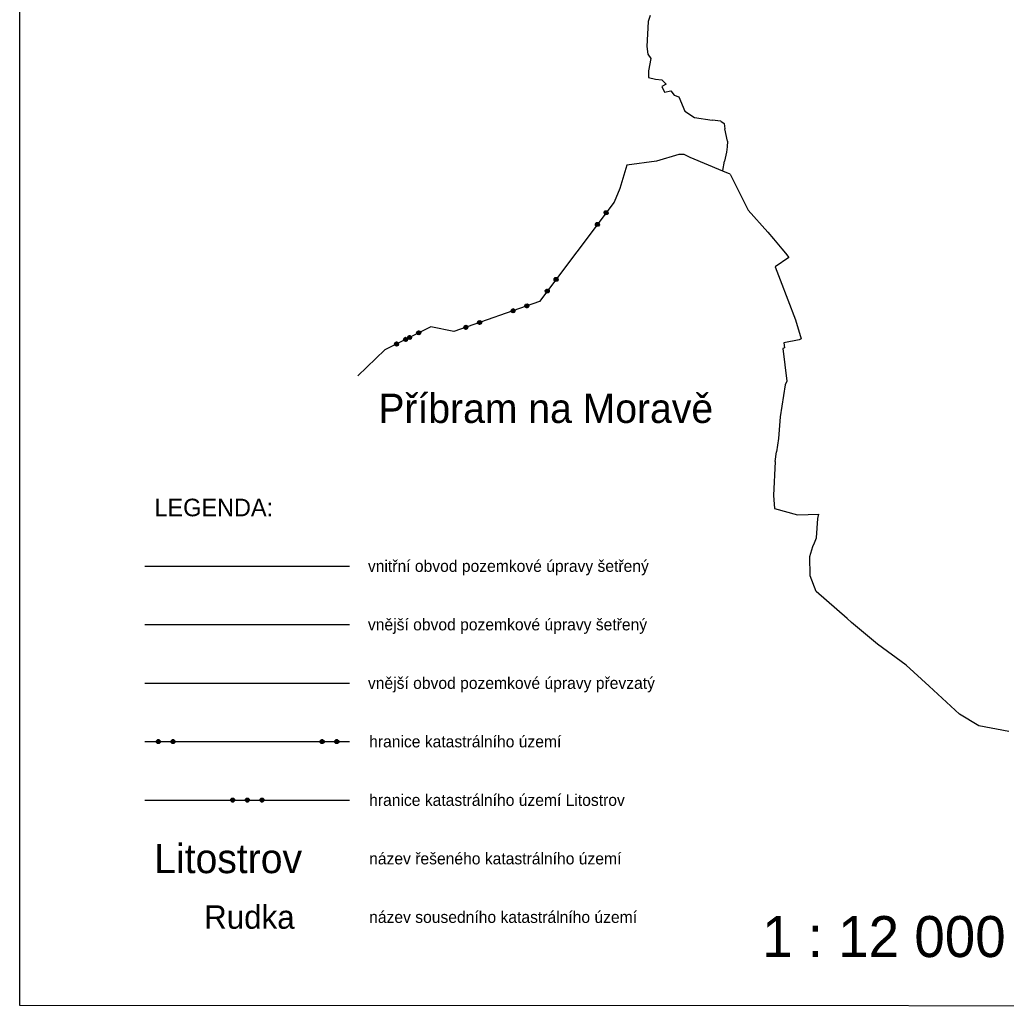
# Model space of a CAD drawing. Extents: x -619641 to -615981, y -1158223 to -1153120.
# Drawn here: x -619641 to -617618, y -1158223 to -1156200 of the extents above; entities that cross this region are included whole.
import ezdxf

# ---------------------------------------------------------------- set-up
doc = ezdxf.new("R2010")
doc.units = 0
for name, color, linetype in [('HRA_KU', 7, 'Continuous'), ('LEGENDA', 7, 'Continuous'), ('Level 255', 7, 'Continuous'), ('POPIS', 7, 'Continuous'), ('RAM', 7, 'Continuous')]:
    doc.layers.add(name, color=color, linetype=linetype)

msp = doc.modelspace()

# ---------------------------------------------------------------- linework, layer by layer
at = {"layer": 'HRA_KU'}
for p, q in [((-618347.7, -1156190.9), (-618352.3, -1156203.8)), ((-618352.3, -1156203.8), (-618355, -1156255.1)), ((-618355, -1156255.1), (-618353, -1156270.5)), ((-618353, -1156270.5), (-618346.8, -1156279.5)), ((-618346.8, -1156279.5), (-618351.4, -1156304.8)), ((-618351.4, -1156304.8), (-618351.7, -1156318.1)), ((-618351.7, -1156318.1), (-618337.3, -1156322.1)), ((-618337.3, -1156322.1), (-618323.8, -1156323.4)), ((-618323.8, -1156323.4), (-618314.9, -1156331.8)), ((-618314.9, -1156331.8), (-618323.8, -1156336.6)), ((-618323.8, -1156336.6), (-618318.3, -1156348.3)), ((-618318.3, -1156348.3), (-618305.6, -1156345.7)), ((-618305.6, -1156345.7), (-618298.5, -1156354.8)), ((-618298.5, -1156354.8), (-618289, -1156357.8)), ((-618289, -1156357.8), (-618277.1, -1156387.6)), ((-618277.1, -1156387.6), (-618256.9, -1156400.6)), ((-618256.9, -1156400.6), (-618221, -1156406.2)), ((-618203.3, -1156408), (-618221, -1156406.2)), ((-618203.3, -1156408), (-618195.9, -1156412.8)), ((-618195.9, -1156412.8), (-618194.5, -1156423.7)), ((-618189.1, -1156449.2), (-618194.5, -1156423.7)), ((-618189.1, -1156449.2), (-618189.8, -1156460.4)), ((-618191.3, -1156471.6), (-618195.4, -1156490.1)), ((-618189.8, -1156460.4), (-618191.3, -1156471.6)), ((-618198.8, -1156508.9), (-618195.4, -1156490.1)), ((-618199.1, -1156510.7), (-618198.8, -1156508.9)), ((-618184.2, -1156516.9), (-618199.1, -1156510.7)), ((-618184.2, -1156516.9), (-618146.7, -1156590.3)), ((-618146.7, -1156590.3), (-618106.3, -1156635.9)), ((-618106.3, -1156635.9), (-618095.2, -1156649.2)), ((-618095.2, -1156649.2), (-618077.9, -1156669.9)), ((-618077.9, -1156669.9), (-618070.4, -1156679)), ((-618063.2, -1156687.6), (-618091.8, -1156706.9)), ((-618070.4, -1156679), (-618063.2, -1156687.6)), ((-618091.8, -1156706.9), (-618081.1, -1156733.3)), ((-618081.1, -1156733.3), (-618050, -1156815.1)), ((-618050, -1156815.1), (-618038, -1156854.2)), ((-618042.6, -1156856.2), (-618074.1, -1156862.7)), ((-618038, -1156854.2), (-618042.6, -1156856.2)), ((-618072.3, -1156872.8), (-618075.7, -1156874.2)), ((-618075.7, -1156874.2), (-618067.8, -1156941.1)), ((-618074.1, -1156862.7), (-618072.3, -1156872.8)), ((-618071.2, -1156948.6), (-618081.2, -1157014.1)), ((-618067.8, -1156941.1), (-618071.2, -1156948.6)), ((-618081.2, -1157014.1), (-618084.5, -1157059.1)), ((-618084.5, -1157059.1), (-618088.8, -1157086)), ((-618091.4, -1157106.2), (-618088.8, -1157086)), ((-618091.4, -1157106.2), (-618095.1, -1157175.7)), ((-618095.1, -1157175.7), (-618093, -1157202.7)), ((-618093, -1157202.7), (-618045.9, -1157215.6)), ((-618045.9, -1157215.6), (-618001.7, -1157214)), ((-618006.8, -1157262.8), (-618004, -1157223.1)), ((-618004, -1157223.1), (-618001.7, -1157214)), ((-618010.9, -1157272.5), (-618006.8, -1157262.8)), ((-618020.7, -1157300.6), (-618014.3, -1157280.4)), ((-618014.3, -1157280.4), (-618010.9, -1157272.5)), ((-618019.7, -1157340.2), (-618020.7, -1157300.6)), ((-618007.4, -1157372.9), (-618019.7, -1157340.2)), ((-617944.1, -1157428.2), (-618007.4, -1157372.9)), ((-617934.7, -1157436.1), (-617944.1, -1157428.2)), ((-617881.5, -1157480.6), (-617934.7, -1157436.1)), ((-617822.7, -1157523.6), (-617881.5, -1157480.6)), ((-617775.7, -1157566.9), (-617822.7, -1157523.6)), ((-617713.4, -1157624.2), (-617775.7, -1157566.9)), ((-617673.7, -1157647.9), (-617713.4, -1157624.2)), ((-617612, -1157659.7), (-617673.7, -1157647.9))]:
    msp.add_line(p, q, dxfattribs=at)
for points in [[(-618199.1, -1156510.7), (-618266.1, -1156482.7), (-618278.3, -1156476.6), (-618289.1, -1156476.5), (-618335, -1156489.7), (-618396, -1156498.4), (-618410.2, -1156545.8), (-618421.7, -1156573.8), (-618574.8, -1156777.7), (-618750.9, -1156839.6), (-618798.2, -1156829.7), (-618891.9, -1156877.1), (-618947.7, -1156930.5)], [(-618436.1, -1156599.4), (-618439.3, -1156599.8), (-618441.9, -1156597.9), (-618442.3, -1156594.7), (-618440.4, -1156592.1), (-618437.2, -1156591.7), (-618434.6, -1156593.6), (-618434.2, -1156596.8), (-618436.1, -1156599.4), (-618436.4, -1156599), (-618434.7, -1156596.7), (-618434.9, -1156595.4), (-618437.8, -1156599.2), (-618439.1, -1156599.4), (-618435.1, -1156594), (-618435.8, -1156593.4), (-618439.9, -1156598.8), (-618440.6, -1156598.2), (-618436.6, -1156592.9), (-618437.4, -1156592.3), (-618441.4, -1156597.7), (-618441.6, -1156596.3), (-618438.7, -1156592.5), (-618440.1, -1156592.7), (-618441.8, -1156595)], [(-618454.1, -1156623.4), (-618457.3, -1156623.8), (-618459.9, -1156621.9), (-618460.4, -1156618.7), (-618458.4, -1156616.1), (-618455.2, -1156615.6), (-618452.6, -1156617.6), (-618452.2, -1156620.8), (-618454.1, -1156623.4), (-618454.3, -1156622.8), (-618452.6, -1156620.5), (-618452.8, -1156619.2), (-618455.6, -1156623), (-618457, -1156623.2), (-618452.9, -1156617.8), (-618453.7, -1156617.2), (-618457.7, -1156622.6), (-618458.5, -1156622), (-618454.5, -1156616.7), (-618455.2, -1156616.1), (-618459.3, -1156621.5), (-618459.5, -1156620.1), (-618456.6, -1156616.3), (-618457.9, -1156616.5), (-618459.7, -1156618.8)], [(-618538.8, -1156736.2), (-618542, -1156736.6), (-618544.6, -1156734.7), (-618545.1, -1156731.5), (-618543.1, -1156728.9), (-618539.9, -1156728.4), (-618537.3, -1156730.4), (-618536.9, -1156733.6), (-618538.8, -1156736.2), (-618539.2, -1156735.8), (-618537.4, -1156733.5), (-618537.6, -1156732.1), (-618540.5, -1156736), (-618541.8, -1156736.2), (-618537.8, -1156730.8), (-618538.6, -1156730.2), (-618542.6, -1156735.6), (-618543.4, -1156735), (-618539.3, -1156729.6), (-618540.1, -1156729.1), (-618544.1, -1156734.4), (-618544.3, -1156733.1), (-618541.5, -1156729.3), (-618542.8, -1156729.4), (-618544.5, -1156731.7)], [(-618556.9, -1156760.2), (-618560.1, -1156760.6), (-618562.6, -1156758.7), (-618563.1, -1156755.5), (-618561.2, -1156752.9), (-618558, -1156752.4), (-618555.4, -1156754.4), (-618554.9, -1156757.6), (-618556.9, -1156760.2), (-618557, -1156759.6), (-618555.3, -1156757.3), (-618555.5, -1156755.9), (-618558.4, -1156759.8), (-618559.7, -1156760), (-618555.7, -1156754.6), (-618556.5, -1156754), (-618560.5, -1156759.4), (-618561.3, -1156758.8), (-618557.2, -1156753.4), (-618558, -1156752.9), (-618562, -1156758.2), (-618562.2, -1156756.9), (-618559.3, -1156753), (-618560.7, -1156753.2), (-618562.4, -1156755.5)], [(-618629.4, -1156800.9), (-618632.3, -1156799.5), (-618633.4, -1156796.5), (-618632, -1156793.6), (-618628.9, -1156792.5), (-618626, -1156793.9), (-618624.9, -1156797), (-618626.3, -1156799.9), (-618629.4, -1156800.9), (-618629.2, -1156800.4), (-618626.5, -1156799.4), (-618625.9, -1156798.2), (-618630.4, -1156799.8), (-618631.7, -1156799.2), (-618625.3, -1156797), (-618625.6, -1156796.1), (-618632, -1156798.3), (-618632.3, -1156797.4), (-618626, -1156795.2), (-618626.3, -1156794.2), (-618632.6, -1156796.5), (-618632, -1156795.2), (-618627.5, -1156793.7), (-618628.7, -1156793.1), (-618631.4, -1156794)], [(-618601.1, -1156791), (-618604, -1156789.6), (-618605.1, -1156786.6), (-618603.7, -1156783.6), (-618600.6, -1156782.6), (-618597.7, -1156784), (-618596.6, -1156787), (-618598, -1156789.9), (-618601.1, -1156791), (-618601.1, -1156790.5), (-618598.4, -1156789.6), (-618597.8, -1156788.3), (-618602.4, -1156789.9), (-618603.6, -1156789.3), (-618597.2, -1156787.1), (-618597.6, -1156786.2), (-618603.9, -1156788.4), (-618604.2, -1156787.5), (-618597.9, -1156785.3), (-618598.2, -1156784.4), (-618604.5, -1156786.6), (-618603.9, -1156785.4), (-618599.4, -1156783.8), (-618600.6, -1156783.2), (-618603.4, -1156784.2)], [(-618697.9, -1156825), (-618700.8, -1156823.6), (-618701.9, -1156820.6), (-618700.5, -1156817.7), (-618697.4, -1156816.6), (-618694.5, -1156818), (-618693.5, -1156821), (-618694.9, -1156823.9), (-618697.9, -1156825), (-618698, -1156824.5), (-618695.2, -1156823.6), (-618694.7, -1156822.4), (-618699.2, -1156823.9), (-618700.4, -1156823.4), (-618694.1, -1156821.1), (-618694.4, -1156820.2), (-618700.7, -1156822.4), (-618701, -1156821.5), (-618694.7, -1156819.3), (-618695, -1156818.4), (-618701.4, -1156820.6), (-618700.8, -1156819.4), (-618696.2, -1156817.8), (-618697.5, -1156817.2), (-618700.2, -1156818.2)], [(-618822.5, -1156846.3), (-618825.6, -1156845.3), (-618827, -1156842.4), (-618826, -1156839.3), (-618823.1, -1156837.8), (-618820.1, -1156838.8), (-618818.6, -1156841.7), (-618819.6, -1156844.8), (-618822.5, -1156846.3), (-618822.6, -1156845.8), (-618820.1, -1156844.5), (-618819.6, -1156843.2), (-618823.9, -1156845.4), (-618825.2, -1156844.9), (-618819.2, -1156841.9), (-618819.6, -1156841), (-618825.6, -1156844.1), (-618826.1, -1156843.2), (-618820.1, -1156840.2), (-618820.5, -1156839.3), (-618826.5, -1156842.4), (-618826.1, -1156841.1), (-618821.8, -1156838.9), (-618823.1, -1156838.5), (-618825.7, -1156839.8)], [(-618726.2, -1156835), (-618729.1, -1156833.6), (-618730.2, -1156830.5), (-618728.8, -1156827.6), (-618725.8, -1156826.5), (-618722.8, -1156827.9), (-618721.8, -1156831), (-618723.2, -1156833.9), (-618726.2, -1156835), (-618726, -1156834.4), (-618723.3, -1156833.4), (-618722.7, -1156832.2), (-618727.3, -1156833.8), (-618728.5, -1156833.2), (-618722.2, -1156831), (-618722.5, -1156830.1), (-618728.8, -1156832.3), (-618729.1, -1156831.4), (-618722.8, -1156829.2), (-618723.1, -1156828.3), (-618729.4, -1156830.5), (-618728.9, -1156829.3), (-618724.3, -1156827.7), (-618725.6, -1156827.1), (-618728.3, -1156828)], [(-618849.3, -1156859.8), (-618852.3, -1156858.8), (-618853.8, -1156855.9), (-618852.8, -1156852.8), (-618849.9, -1156851.4), (-618846.8, -1156852.4), (-618845.4, -1156855.3), (-618846.4, -1156858.3), (-618849.3, -1156859.8), (-618849.2, -1156859.2), (-618846.6, -1156857.9), (-618846.2, -1156856.6), (-618850.5, -1156858.8), (-618851.8, -1156858.4), (-618845.8, -1156855.3), (-618846.2, -1156854.5), (-618852.2, -1156857.5), (-618852.6, -1156856.7), (-618846.6, -1156853.6), (-618847.1, -1156852.8), (-618853.1, -1156855.8), (-618852.6, -1156854.5), (-618848.3, -1156852.3), (-618849.6, -1156851.9), (-618852.2, -1156853.2)], [(-618841.2, -1156855.7), (-618844.3, -1156854.7), (-618845.7, -1156851.8), (-618844.7, -1156848.8), (-618841.8, -1156847.3), (-618838.8, -1156848.3), (-618837.3, -1156851.2), (-618838.3, -1156854.3), (-618841.2, -1156855.7), (-618841.3, -1156855.2), (-618838.7, -1156853.9), (-618838.3, -1156852.6), (-618842.6, -1156854.8), (-618843.9, -1156854.4), (-618837.9, -1156851.4), (-618838.3, -1156850.5), (-618844.3, -1156853.5), (-618844.8, -1156852.7), (-618838.8, -1156849.6), (-618839.2, -1156848.8), (-618845.2, -1156851.8), (-618844.8, -1156850.5), (-618840.5, -1156848.4), (-618841.8, -1156847.9), (-618844.3, -1156849.2)], [(-618868, -1156869.3), (-618871, -1156868.3), (-618872.5, -1156865.4), (-618871.5, -1156862.3), (-618868.6, -1156860.8), (-618865.5, -1156861.8), (-618864.1, -1156864.7), (-618865.1, -1156867.8), (-618868, -1156869.3), (-618867.9, -1156868.7), (-618865.3, -1156867.4), (-618864.9, -1156866.1), (-618869.2, -1156868.2), (-618870.4, -1156867.8), (-618864.4, -1156864.8), (-618864.9, -1156863.9), (-618870.9, -1156867), (-618871.3, -1156866.1), (-618865.3, -1156863.1), (-618865.7, -1156862.2), (-618871.7, -1156865.3), (-618871.3, -1156864), (-618867, -1156861.8), (-618868.3, -1156861.4), (-618870.9, -1156862.7)]]:
    msp.add_lwpolyline(points, dxfattribs=at)
at = {"layer": 'LEGENDA'}
for p, q in [((-619384.4, -1157320.3), (-618964.4, -1157320.3)), ((-619384.4, -1157440.3), (-618964.4, -1157440.3)), ((-619384.4, -1157560.3), (-618964.4, -1157560.3)), ((-619384.4, -1157680.3), (-618964.4, -1157680.3))]:
    msp.add_line(p, q, dxfattribs=at)
for points in [[(-619355.2, -1157676.5), (-619352.9, -1157678.7), (-619352.9, -1157682), (-619355.2, -1157684.3), (-619358.5, -1157684.3), (-619360.7, -1157682), (-619360.7, -1157678.7), (-619358.5, -1157676.5), (-619355.2, -1157676.5), (-619355.3, -1157676.9), (-619358.2, -1157676.9), (-619359.2, -1157677.9), (-619354.4, -1157677.9), (-619353.4, -1157678.9), (-619360.1, -1157678.9), (-619360.1, -1157679.8), (-619353.4, -1157679.8), (-619353.4, -1157680.8), (-619360.1, -1157680.8), (-619360.1, -1157681.7), (-619353.4, -1157681.7), (-619354.4, -1157682.7), (-619359.2, -1157682.7), (-619358.2, -1157683.7), (-619355.3, -1157683.7)], [(-619325.2, -1157676.5), (-619322.9, -1157678.7), (-619322.9, -1157682), (-619325.2, -1157684.3), (-619328.5, -1157684.3), (-619330.7, -1157682), (-619330.7, -1157678.7), (-619328.5, -1157676.5), (-619325.2, -1157676.5), (-619325.6, -1157676.9), (-619328.5, -1157676.9), (-619329.4, -1157677.9), (-619324.6, -1157677.9), (-619323.7, -1157678.9), (-619330.4, -1157678.9), (-619330.4, -1157679.8), (-619323.7, -1157679.8), (-619323.7, -1157680.8), (-619330.4, -1157680.8), (-619330.4, -1157681.7), (-619323.7, -1157681.7), (-619324.6, -1157682.7), (-619329.4, -1157682.7), (-619328.5, -1157683.7), (-619325.6, -1157683.7)], [(-619019.2, -1157676.5), (-619016.9, -1157678.7), (-619016.9, -1157682), (-619019.2, -1157684.3), (-619022.5, -1157684.3), (-619024.7, -1157682), (-619024.7, -1157678.7), (-619022.5, -1157676.5), (-619019.2, -1157676.5), (-619019.3, -1157676.9), (-619022.2, -1157676.9), (-619023.2, -1157677.9), (-619018.4, -1157677.9), (-619017.4, -1157678.9), (-619024.1, -1157678.9), (-619024.1, -1157679.8), (-619017.4, -1157679.8), (-619017.4, -1157680.8), (-619024.1, -1157680.8), (-619024.1, -1157681.7), (-619017.4, -1157681.7), (-619018.4, -1157682.7), (-619023.2, -1157682.7), (-619022.2, -1157683.7), (-619019.3, -1157683.7)], [(-618989.2, -1157676.5), (-618986.9, -1157678.7), (-618986.9, -1157682), (-618989.2, -1157684.3), (-618992.5, -1157684.3), (-618994.7, -1157682), (-618994.7, -1157678.7), (-618992.5, -1157676.5), (-618989.2, -1157676.5), (-618989.6, -1157676.9), (-618992.5, -1157676.9), (-618993.4, -1157677.9), (-618988.6, -1157677.9), (-618987.7, -1157678.9), (-618994.4, -1157678.9), (-618994.4, -1157679.8), (-618987.7, -1157679.8), (-618987.7, -1157680.8), (-618994.4, -1157680.8), (-618994.4, -1157681.7), (-618987.7, -1157681.7), (-618988.6, -1157682.7), (-618993.4, -1157682.7), (-618992.5, -1157683.7), (-618989.6, -1157683.7)], [(-619202.8, -1157796.5), (-619200.5, -1157798.7), (-619200.5, -1157802), (-619202.8, -1157804.3), (-619206.1, -1157804.3), (-619208.3, -1157802), (-619208.3, -1157798.7), (-619206.1, -1157796.5), (-619202.8, -1157796.5), (-619202.7, -1157796.9), (-619205.6, -1157796.9), (-619206.5, -1157797.9), (-619201.7, -1157797.9), (-619201, -1157798.9), (-619207.5, -1157798.9), (-619207.5, -1157799.8), (-619201.1, -1157799.8), (-619201, -1157800.8), (-619207.4, -1157800.8), (-619207.4, -1157801.7), (-619201, -1157801.7), (-619201.6, -1157802.7), (-619206.8, -1157802.7), (-619205.9, -1157803.7), (-619202.6, -1157803.7)], [(-619172.7, -1157796.5), (-619170.4, -1157798.7), (-619170.4, -1157802), (-619172.7, -1157804.3), (-619175.9, -1157804.3), (-619178.2, -1157802), (-619178.2, -1157798.7), (-619175.9, -1157796.5), (-619172.7, -1157796.5), (-619172.8, -1157796.9), (-619175.7, -1157796.9), (-619176.7, -1157797.9), (-619171.9, -1157797.9), (-619170.9, -1157798.9), (-619177.6, -1157798.9), (-619177.6, -1157799.8), (-619170.9, -1157799.8), (-619170.9, -1157800.8), (-619177.6, -1157800.8), (-619177.6, -1157801.7), (-619170.9, -1157801.7), (-619171.9, -1157802.7), (-619176.7, -1157802.7), (-619175.7, -1157803.7), (-619172.8, -1157803.7)], [(-619142.6, -1157796.5), (-619140.3, -1157798.7), (-619140.3, -1157802), (-619142.6, -1157804.3), (-619145.8, -1157804.3), (-619148.1, -1157802), (-619148.1, -1157798.7), (-619145.8, -1157796.5), (-619142.6, -1157796.5), (-619143.1, -1157796.9), (-619145.9, -1157796.9), (-619146.7, -1157797.9), (-619142.1, -1157797.9), (-619141.1, -1157798.9), (-619147.4, -1157798.9), (-619147.4, -1157799.8), (-619141.1, -1157799.8), (-619141.1, -1157800.8), (-619147.4, -1157800.8), (-619147.5, -1157801.7), (-619141.3, -1157801.7), (-619141.7, -1157802.7), (-619146.7, -1157802.7), (-619146.1, -1157803.7), (-619143.2, -1157803.7)]]:
    msp.add_lwpolyline(points, dxfattribs=at)
at = {"layer": 'Level 255'}
msp.add_line((-619384.4, -1157800.3), (-618964.4, -1157800.3), dxfattribs=at)
at = {"layer": 'RAM'}
msp.add_lwpolyline([(-619640.7, -1153120.4), (-615980.9, -1153121), (-615994.3, -1158223.3), (-619641.1, -1158221.6), (-619640.7, -1153120.4)], dxfattribs=at)

# ---------------------------------------------------------------- texts
at = {"layer": 'Level 255'}
for s, height, p in [('Příbram na Moravě', 60, (-618905.5, -1157026.9)), ('LEGENDA:', 36, (-619364.8, -1157218.3)), ('vnitřní obvod pozemkové úpravy šetřený', 24, (-618926.9, -1157332.3)), ('vnější obvod pozemkové úpravy šetřený', 24, (-618926.9, -1157452.3)), ('vnější obvod pozemkové úpravy převzatý', 24, (-618926.9, -1157572.3)), ('hranice katastrálního území ', 24, (-618924.4, -1157692.3)), ('hranice katastrálního území Litostrov', 24, (-618924.4, -1157812.3)), ('Litostrov', 60, (-619365.2, -1157950.3)), ('název řešeného katastrálního území', 24, (-618924.4, -1157932.3)), ('Rudka', 48, (-619262.8, -1158064.3)), ('název sousedního katastrálního území', 24, (-618924.4, -1158052.3))]:
    msp.add_text(s, height=height, dxfattribs=at).set_placement(p)
at = {"layer": 'POPIS'}
msp.add_text('1 : 12 000', height=84, dxfattribs=at).set_placement((-618118.4, -1158122.3))

doc.saveas('drawing.dxf')
